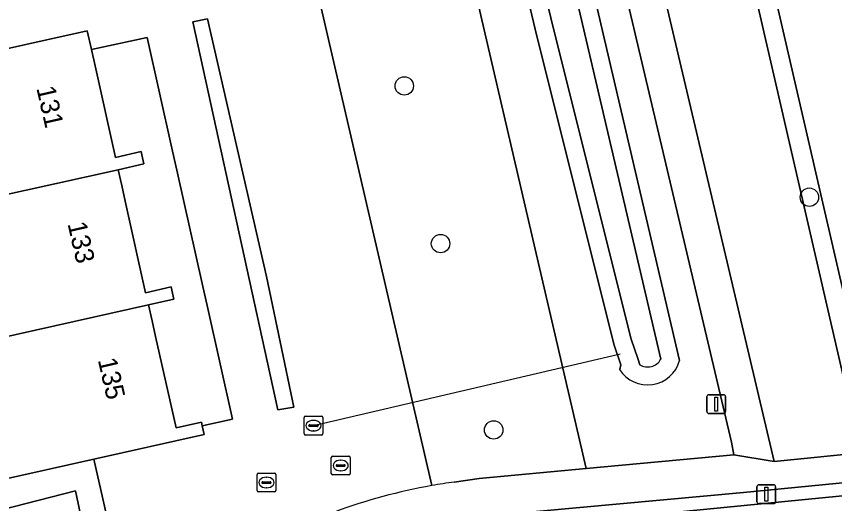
# Model space of a CAD drawing. Extents: x 156661 to 157576, y 383570 to 384425.
# Drawn here: x 156829.98 to 156873.33, y 383918.12 to 383943.95 of the extents above; entities that cross this region are included whole.
import ezdxf

# ---------------------------------------------------------------- set-up
doc = ezdxf.new("R2010")
doc.units = 0
for name, color, linetype in [('IMGEO_Berm_groen', 7, 'Continuous'), ('IMGEO_Boom', 7, 'Continuous'), ('IMGEO_Duiker', 7, 'Continuous'), ('IMGEO_Erf', 7, 'Continuous'), ('IMGEO_Groenvoorziening', 7, 'Continuous'), ('IMGEO_Haag', 7, 'Continuous'), ('IMGEO_Lichtmast', 7, 'Continuous'), ('IMGEO_Muur', 7, 'Continuous'), ('IMGEO_Oever', 7, 'Continuous'), ('IMGEO_Pand', 7, 'Continuous'), ('IMGEO_Pand_nummerreeks', 7, 'Continuous'), ('IMGEO_Parkeervlak_open', 7, 'Continuous'), ('IMGEO_Rioolput', 7, 'Continuous'), ('IMGEO_Voetpad_open', 7, 'Continuous'), ('IMGEO_Waterloop', 7, 'Continuous')]:
    doc.layers.add(name, color=color, linetype=linetype)

msp = doc.modelspace()

# ---------------------------------------------------------------- linework, layer by layer
at = {"layer": 'IMGEO_Berm_groen'}
msp.add_lwpolyline([(156853.805, 383916.581), (156939.653, 383925.02), (156939.883, 383922.625), (156942.261, 383922.858), (156942.029, 383925.893), (156868.496, 383918.711), (156853.282, 383917.324)], dxfattribs=at)
at = {"layer": 'IMGEO_Boom'}
for centre in [(156850.53, 383940.266), (156871.988, 383934.368), (156852.452, 383931.908), (156855.267, 383922.031)]:
    msp.add_circle(centre, 0.489, dxfattribs=at)
at = {"layer": 'IMGEO_Duiker'}
msp.add_lwpolyline([(156845.721, 383922.26), (156861.821, 383926.028), (156861.958, 383926.06)], dxfattribs=at)
at = {"layer": 'IMGEO_Erf'}
msp.add_lwpolyline([(156836.909, 383942.836), (156833.955, 383942.205), (156834.15, 383941.33), (156835.23, 383936.476), (156836.586, 383936.783), (156836.622, 383936.62), (156836.733, 383936.134), (156835.377, 383935.827), (156835.564, 383934.988), (156835.747, 383934.165), (156836.831, 383929.302), (156838.186, 383929.613), (156838.226, 383929.438), (156838.333, 383928.97), (156836.979, 383928.659), (156837.169, 383927.81), (156837.355, 383926.98), (156838.44, 383922.142), (156839.787, 383922.442), (156839.83, 383922.252), (156841.425, 383922.608), (156840.117, 383928.468), (156839.821, 383929.794), (156838.514, 383935.647), (156838.218, 383936.976)], close=True, dxfattribs=at)
at = {"layer": 'IMGEO_Groenvoorziening'}
for points in [[(156825.282, 384070.084), (156860.158, 383919.98), (156867.979, 383920.714), (156867.866, 383921.383), (156832.423, 384071.718)], [(156954.897, 383930.297), (156954.665, 383931.279), (156875.116, 383923.557), (156857.538, 383999.895), (156855.447, 384008.779), (156854.961, 384008.661), (156854.475, 384008.544), (156856.565, 383999.666), (156874.225, 383922.969), (156874.338, 383922.477), (156874.835, 383922.525)], [(156874.835, 383922.525), (156874.338, 383922.477), (156874.225, 383922.969), (156856.565, 383999.666), (156854.475, 384008.544), (156851.846, 384007.908), (156849.631, 384007.372), (156870.13, 383920.364), (156875.218, 383920.862)], [(156844.675, 383923.242), (156843.226, 383930.161), (156840.106, 383943.823), (156839.33, 383943.662), (156843.829, 383923.092)], [(156840.106, 383943.823), (156843.226, 383930.161), (156844.675, 383923.242), (156843.829, 383923.092), (156839.33, 383943.662)]]:
    msp.add_lwpolyline(points, close=True, dxfattribs=at)
for points in [[(156853.18, 383919.265), (156854.491, 383919.448), (156860.158, 383919.98), (156825.282, 384070.084), (156817.43, 384068.287), (156851.989, 383919.079)], [(156851.989, 383919.079), (156817.43, 384068.287)], [(156836.685, 384046.556), (156846.808, 384004.086), (156865.113, 383925.704)], [(156861.939, 383925.229), (156862.009, 383925.475), (156861.632, 383926.582), (156857.459, 383943.277), (156846.139, 383990.769), (156837.808, 384026.146), (156834.432, 384042.083), (156834.089, 384043.235), (156833.431, 384045.96)], [(156971.825, 384035.574), (156971.462, 384036.848), (156855.447, 384008.779), (156857.538, 383999.895), (156875.116, 383923.557), (156954.665, 383931.279), (156953.099, 383937.896)], [(156823.818, 383940.987), (156833.736, 383943.193), (156833.955, 383942.205), (156836.909, 383942.836), (156838.218, 383936.976), (156838.514, 383935.647), (156839.821, 383929.794), (156840.117, 383928.468), (156841.425, 383922.608), (156839.83, 383922.252), (156839.933, 383921.788), (156834.083, 383920.486), (156836.167, 383911.298), (156836.719, 383911.755)], [(156820.131, 383898.001), (156834.922, 383910.265), (156833.107, 383918.804), (156829.202, 383917.794), (156823.434, 383916.512), (156820.398, 383915.844), (156817.468, 383915.2), (156816.817, 383918.128), (156816.732, 383918.51), (156810.873, 383917.164), (156812.023, 383911.93), (156814.996, 383912.584), (156815.273, 383911.078), (156812.396, 383910.435), (156812.552, 383909.758)]]:
    msp.add_lwpolyline(points, dxfattribs=at)
for centre, radius, start, end in [((156863.42, 383926.172), 1.756, 212.4689, 344.5538), ((156857.204, 383889.617), 29.92, 100.0386, 110.2044), ((156857.251, 383889.291), 30.249, 97.7345, 100.018)]:
    msp.add_arc(centre, radius, start, end, dxfattribs=at)
at = {"layer": 'IMGEO_Haag'}
for points in [[(156857.538, 383999.895), (156855.447, 384008.779), (156854.961, 384008.661), (156854.475, 384008.544), (156856.565, 383999.666), (156874.225, 383922.969), (156874.338, 383922.477), (156874.835, 383922.525), (156954.897, 383930.297), (156954.665, 383931.279), (156875.116, 383923.557)], [(156844.675, 383923.242), (156843.226, 383930.161), (156840.106, 383943.823), (156839.33, 383943.662), (156843.829, 383923.092)]]:
    msp.add_lwpolyline(points, close=True, dxfattribs=at)
at = {"layer": 'IMGEO_Lichtmast'}
for p, q in [((156866.557, 383923), (156866.557, 383923.8)), ((156866.557, 383923.8), (156866.557, 383923)), ((156866.657, 383923.9), (156867.447, 383923.9)), ((156867.447, 383923.9), (156866.657, 383923.9)), ((156867.547, 383923.8), (156867.547, 383923)), ((156867.547, 383923), (156867.547, 383923.8)), ((156867.447, 383922.9), (156866.657, 383922.9)), ((156866.657, 383922.9), (156867.447, 383922.9)), ((156869.211, 383918.223), (156869.211, 383919.023)), ((156869.211, 383919.023), (156869.211, 383918.223)), ((156869.311, 383919.123), (156870.101, 383919.123)), ((156870.101, 383919.123), (156869.311, 383919.123)), ((156870.201, 383919.023), (156870.201, 383918.223)), ((156870.201, 383918.223), (156870.201, 383919.023)), ((156870.101, 383918.123), (156869.311, 383918.123)), ((156869.311, 383918.123), (156870.101, 383918.123))]:
    msp.add_line(p, q, dxfattribs=at)
for points in [[(156866.977, 383923.775), (156867.127, 383923.775), (156867.127, 383923.025), (156866.977, 383923.025), (156866.977, 383923.775)], [(156869.631, 383918.998), (156869.781, 383918.998), (156869.781, 383918.248), (156869.631, 383918.248), (156869.631, 383918.998)]]:
    msp.add_lwpolyline(points, dxfattribs=at)
for centre, start, end in [((156866.657, 383923.8), 90, 180), ((156866.657, 383923.8), 90, 180), ((156867.447, 383923.8), 0, 90), ((156867.447, 383923.8), 360, 90), ((156866.657, 383923), 180, 270), ((156866.657, 383923), 180, 270), ((156867.447, 383923), 270, 0), ((156867.447, 383923), 270, 0), ((156869.311, 383919.023), 90, 180), ((156869.311, 383919.023), 90, 180), ((156870.101, 383919.023), 0, 90), ((156870.101, 383919.023), 360, 90), ((156869.311, 383918.223), 180, 270), ((156869.311, 383918.223), 180, 270), ((156870.101, 383918.223), 270, 0), ((156870.101, 383918.223), 270, 0)]:
    msp.add_arc(centre, 0.1, start, end, dxfattribs=at)
at = {"layer": 'IMGEO_Muur'}
for points in [[(156833.955, 383942.205), (156836.909, 383942.836), (156838.218, 383936.976)], [(156838.514, 383935.647), (156839.821, 383929.794)], [(156840.117, 383928.468), (156841.425, 383922.608), (156839.83, 383922.252)]]:
    msp.add_lwpolyline(points, dxfattribs=at)
at = {"layer": 'IMGEO_Oever'}
for points in [[(156835.811, 384046.116), (156845.881, 384003.867), (156864.119, 383925.774)], [(156833.431, 384045.96), (156834.089, 384043.235), (156834.432, 384042.083), (156837.808, 384026.146), (156846.139, 383990.769), (156857.459, 383943.277), (156861.632, 383926.582), (156862.009, 383925.475), (156861.939, 383925.229)], [(156863.002, 383925.486), (156862.901, 383925.812), (156862.546, 383926.851), (156858.384, 383943.503), (156847.066, 383990.989), (156838.738, 384026.354), (156835.356, 384042.318), (156835.009, 384043.483), (156834.425, 384045.9)], [(156865.113, 383925.704), (156846.808, 384004.086)]]:
    msp.add_lwpolyline(points, dxfattribs=at)
for centre, radius, start, end in [((156863.42, 383926.172), 1.756, 212.4689, 344.5538), ((156863.42, 383926.173), 0.805, 238.6586, 330.2572)]:
    msp.add_arc(centre, radius, start, end, dxfattribs=at)
at = {"layer": 'IMGEO_Pand'}
for points in [[(156835.377, 383935.827), (156836.733, 383936.134), (156836.622, 383936.62), (156836.586, 383936.783), (156835.23, 383936.476), (156834.15, 383941.33), (156833.955, 383942.205), (156833.736, 383943.193), (156823.818, 383940.987), (156824.985, 383935.745), (156819.469, 383934.238), (156815.612, 383933.105), (156815.84, 383932.096), (156815.91, 383931.788), (156815.972, 383931.515), (156819.89, 383932.386), (156825.454, 383933.622)], [(156838.333, 383928.97), (156838.226, 383929.438), (156838.186, 383929.613), (156836.831, 383929.302), (156835.747, 383934.165), (156835.564, 383934.988), (156835.377, 383935.827), (156825.454, 383933.622), (156826.57, 383928.572), (156821.097, 383927.076), (156817.17, 383926.204), (156817.228, 383925.944), (156817.522, 383924.626), (156817.584, 383924.35), (156821.518, 383925.224), (156827.04, 383926.444), (156836.979, 383928.659)], [(156837.355, 383926.98), (156837.169, 383927.81), (156836.979, 383928.659), (156827.04, 383926.444), (156828, 383922.163), (156828.648, 383919.276), (156828.862, 383919.324), (156834.083, 383920.486), (156839.933, 383921.788), (156839.83, 383922.252), (156839.787, 383922.442), (156838.44, 383922.142)]]:
    msp.add_lwpolyline(points, close=True, dxfattribs=at)
at = {"layer": 'IMGEO_Parkeervlak_open'}
msp.add_lwpolyline([(156855.097, 383914.318), (156858.629, 383914.671), (156939.883, 383922.625), (156939.653, 383925.02), (156853.805, 383916.581)], dxfattribs=at)
at = {"layer": 'IMGEO_Rioolput'}
for p, q in [((156845.22, 383921.834), (156845.22, 383922.686)), ((156845.295, 383922.76), (156846.147, 383922.76)), ((156845.708, 383922.54), (156845.733, 383922.54)), ((156846.221, 383922.686), (156846.221, 383921.834)), ((156845.479, 383922.254), (156845.479, 383922.266)), ((156845.917, 383922.217), (156845.519, 383922.217)), ((156845.522, 383922.303), (156845.92, 383922.303)), ((156845.963, 383922.266), (156845.963, 383922.254)), ((156846.147, 383921.76), (156845.295, 383921.76)), ((156845.731, 383921.98), (156845.706, 383921.98)), ((156846.663, 383919.718), (156846.663, 383920.57)), ((156846.738, 383920.644), (156847.59, 383920.644)), ((156847.151, 383920.424), (156847.176, 383920.424)), ((156847.664, 383920.57), (156847.664, 383919.718)), ((156846.922, 383920.138), (156846.922, 383920.15)), ((156847.36, 383920.101), (156846.962, 383920.101)), ((156846.965, 383920.187), (156847.363, 383920.187)), ((156847.174, 383919.864), (156847.149, 383919.864)), ((156847.406, 383920.15), (156847.406, 383920.138)), ((156842.731, 383918.817), (156842.731, 383919.669)), ((156842.806, 383919.743), (156843.658, 383919.743)), ((156843.219, 383919.523), (156843.244, 383919.523)), ((156843.732, 383919.669), (156843.732, 383918.817)), ((156847.59, 383919.644), (156846.738, 383919.644)), ((156842.99, 383919.237), (156842.99, 383919.249)), ((156843.428, 383919.2), (156843.03, 383919.2)), ((156843.033, 383919.286), (156843.431, 383919.286)), ((156843.474, 383919.249), (156843.474, 383919.237)), ((156843.658, 383918.743), (156842.806, 383918.743)), ((156843.242, 383918.963), (156843.217, 383918.963))]:
    msp.add_line(p, q, dxfattribs=at)
for points in [[(156845.22, 383921.834), (156845.22, 383922.686)], [(156845.295, 383922.76), (156846.147, 383922.76)], [(156846.221, 383922.686), (156846.221, 383921.834)], [(156846.147, 383921.76), (156845.295, 383921.76)], [(156846.663, 383919.718), (156846.663, 383920.57)], [(156846.738, 383920.644), (156847.59, 383920.644)], [(156847.664, 383920.57), (156847.664, 383919.718)], [(156842.731, 383918.817), (156842.731, 383919.669)], [(156842.806, 383919.743), (156843.658, 383919.743)], [(156843.732, 383919.669), (156843.732, 383918.817)], [(156847.59, 383919.644), (156846.738, 383919.644)], [(156843.658, 383918.743), (156842.806, 383918.743)]]:
    msp.add_lwpolyline(points, dxfattribs=at)
for centre, radius, start, end in [((156845.297, 383922.684), 0.0765, 91.552, 178.448), ((156845.297, 383922.684), 0.0765, 91.552, 178.448), ((156846.145, 383922.684), 0.0765, 1.552, 88.448), ((156846.145, 383922.684), 0.0765, 1.552, 88.448), ((156845.519, 383922.263), 0.0403, 85.8775, 175.7526), ((156845.516, 383922.253), 0.0366, 178.938, 274.7102), ((156845.92, 383922.26), 0.043, 264.8664, 352.4533), ((156845.924, 383922.265), 0.0386, 1.7309, 96.639), ((156845.297, 383921.836), 0.0765, 181.552, 268.448), ((156845.297, 383921.836), 0.0765, 181.552, 268.448), ((156846.145, 383921.836), 0.0765, 271.552, 358.448), ((156846.145, 383921.836), 0.0765, 271.552, 358.448), ((156846.74, 383920.568), 0.0765, 91.552, 178.448), ((156846.74, 383920.568), 0.0765, 91.552, 178.448), ((156847.588, 383920.568), 0.0765, 1.552, 88.448), ((156847.588, 383920.568), 0.0765, 1.552, 88.448), ((156846.962, 383920.147), 0.0403, 85.8775, 175.7526), ((156846.959, 383920.137), 0.0366, 178.938, 274.7102), ((156847.363, 383920.144), 0.043, 264.8664, 352.4533), ((156847.367, 383920.149), 0.0386, 1.7309, 96.639), ((156842.808, 383919.667), 0.0765, 91.552, 178.448), ((156842.808, 383919.667), 0.0765, 91.552, 178.448), ((156843.656, 383919.667), 0.0765, 1.552, 88.448), ((156843.656, 383919.667), 0.0765, 1.552, 88.448), ((156846.74, 383919.72), 0.0765, 181.552, 268.448), ((156846.74, 383919.72), 0.0765, 181.552, 268.448), ((156847.588, 383919.72), 0.0765, 271.552, 358.448), ((156847.588, 383919.72), 0.0765, 271.552, 358.448), ((156843.03, 383919.246), 0.0403, 85.8775, 175.7526), ((156843.027, 383919.236), 0.0366, 178.938, 274.7102), ((156843.431, 383919.243), 0.043, 264.8664, 352.4533), ((156843.435, 383919.248), 0.0386, 1.7309, 96.639), ((156842.808, 383918.819), 0.0765, 181.552, 268.448), ((156842.808, 383918.819), 0.0765, 181.552, 268.448), ((156843.656, 383918.819), 0.0765, 271.552, 358.448), ((156843.656, 383918.819), 0.0765, 271.552, 358.448)]:
    msp.add_arc(centre, radius, start, end, dxfattribs=at)
for centre, major_axis, ratio, start_param, end_param in [((156845.707, 383922.26), (-0.387, 0.002), 0.722429, 4.712389, 7.853982), ((156845.732, 383922.26), (-0.39, 0.002), 0.717154, 1.570796, 4.712389), ((156847.15, 383920.144), (-0.387, 0.002), 0.722429, 4.712389, 7.853982), ((156847.175, 383920.144), (-0.39, 0.002), 0.717154, 1.570796, 4.712389), ((156843.218, 383919.243), (-0.387, 0.002), 0.722429, 4.712389, 7.853982), ((156843.243, 383919.243), (-0.39, 0.002), 0.717154, 1.570796, 4.712389)]:
    msp.add_ellipse(centre, major_axis=major_axis, ratio=ratio, start_param=start_param, end_param=end_param, dxfattribs=at)
at = {"layer": 'IMGEO_Voetpad_open'}
msp.add_lwpolyline([(156849.631, 384007.372), (156849.171, 384009.324), (156834.367, 384072.163), (156832.423, 384071.718), (156867.866, 383921.383), (156867.979, 383920.714), (156870.13, 383920.364)], close=True, dxfattribs=at)
for points in [[(156955.061, 383936.102), (156957.783, 383936.781), (156956.745, 383941.083), (156956.425, 383941.002), (156956.295, 383941.53), (156952.407, 383940.603), (156953.011, 383938.269), (156953.099, 383937.896), (156954.665, 383931.279), (156954.897, 383930.297), (156955.275, 383928.7), (156875.218, 383920.862), (156870.13, 383920.364), (156867.979, 383920.714), (156860.158, 383919.98), (156854.491, 383919.448), (156853.18, 383919.265)], [(156853.282, 383917.324), (156868.496, 383918.711), (156942.029, 383925.893), (156944.032, 383926.112), (156952.092, 383926.89), (156954.952, 383927.178), (156958.753, 383927.533), (156959.604, 383929.198), (156956.799, 383928.862), (156955.061, 383936.102)], [(156836.719, 383911.755), (156836.167, 383911.298), (156834.083, 383920.486), (156828.862, 383919.324), (156829.202, 383917.794), (156833.107, 383918.804), (156834.922, 383910.265), (156820.131, 383898.001)]]:
    msp.add_lwpolyline(points, dxfattribs=at)
for centre, radius, start, end in [((156857.204, 383889.617), 29.92, 100.0386, 110.2044), ((156857.251, 383889.291), 30.249, 97.7345, 100.018)]:
    msp.add_arc(centre, radius, start, end, dxfattribs=at)
at = {"layer": 'IMGEO_Waterloop'}
for points in [[(156834.425, 384045.9), (156835.009, 384043.483), (156835.356, 384042.318), (156838.738, 384026.354), (156847.066, 383990.989), (156858.384, 383943.503), (156862.546, 383926.851), (156862.901, 383925.812), (156863.002, 383925.486)], [(156864.119, 383925.774), (156845.881, 384003.867)]]:
    msp.add_lwpolyline(points, dxfattribs=at)
msp.add_arc((156863.42, 383926.173), 0.805, 238.6586, 330.2572, dxfattribs=at)

# ---------------------------------------------------------------- texts
at = {"layer": 'IMGEO_Pand_nummerreeks'}
for s, rotation, p in [('131', 282.7767, (156831.039, 383940.152)), ('133', 282.9143, (156832.689, 383932.961)), ('135', 283.0575, (156834.293, 383925.743))]:
    msp.add_text(s, height=1, rotation=rotation, dxfattribs=at).set_placement(p)

doc.saveas('drawing.dxf')
